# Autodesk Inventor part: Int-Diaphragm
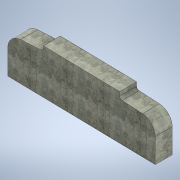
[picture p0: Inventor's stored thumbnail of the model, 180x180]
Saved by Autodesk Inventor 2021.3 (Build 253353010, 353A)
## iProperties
Created: 2021-10
Part Number: Int-Diaphragm
Material: Concrete, Cast-in-Place, Gray
Document SubType Name: Modeling
Designer: u1426
Density: 2.40731 g/cm^3
Appearance: Flat - Gray 1
Author: u1426
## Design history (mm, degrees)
sketch "Sketch1"
  geometry: L1 (-533.4, 681.736)-(-533.4, 623.402); L2 (-497.564, 585.369)-(-191.126, 567.129); L3 (0, 364.288)-(0, 0); L4 (-2209.8, 44.196)-(-2209.8, 411.532); L5 (-1712.236, 632.613)-(-2018.674, 614.373); L6 (-1676.4, 670.646)-(-1676.4, 704.596); L7 (-1676.4, 704.596)-(-533.4, 681.736); L8 (-2209.8, 44.196)-(0, 0); A1 r 203.2 centre (-203.2, 364.288) between (0, 364.288) and (-191.126, 567.129); A2 r 38.1 centre (-495.3, 623.402) between (-533.4, 623.402) and (-497.564, 585.369); A3 r 203.2 centre (-2006.6, 411.532) between (-2018.674, 614.373) and (-2209.8, 411.532); A4 r 38.1 centre (-1714.5, 670.646) between (-1712.236, 632.613) and (-1676.4, 670.646); 5 further points
  constraints: 16 end point, 8 point on circle, 8 point on line, 8 tangent, 4 centre point, 4 vertical, 1 parallel
  dimensions: "d12" = 94.234 distance of L1.start point (-533.4, 587.502) (computed from d42); "d16" = 31.75 vertical distance of point (-533.4, 587.502) point (0, 555.752); "d23" = 203.2 radius of A1; "d24" = 38.1 radius of A2; "d40" = 533.4 horizontal distance of point (-1676.4, 634.746) point (-2209.8, 602.996); "d41" = 31.75 vertical distance of point (-1676.4, 634.746) point (-2209.8, 602.996); "d42" = 69.85 distance of point (-1676.4, 634.746) L6.end; "d59" = 2209.8 horizontal distance of L4.start L3.end; "d62" = 203.2 radius of A3; "d63" = 38.1 radius of A4; "d64" = 0 distance from line of point (0, 0) L3; "d65" = 0 distance of point (0, 0) L3.end; "d68" = 660.4 vertical distance of L4.start L6.end; "d69" = 367.33558 distance of L4.start L4.end (derived); "d71" = 533.4 distance between parallel lines of L3 L1; "d72" = 44.196 vertical distance of L4.start L3.end
extrude "Extrusion3" new body sketch "Sketch1" stored distance "d66" = 254; taper "d67" = 0 deg
body "Solid2"
